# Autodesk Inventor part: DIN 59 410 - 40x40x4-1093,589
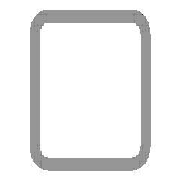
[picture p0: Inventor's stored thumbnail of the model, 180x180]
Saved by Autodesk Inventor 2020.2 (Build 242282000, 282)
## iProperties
Manager: www.cadconsulting.pl
Company: Fabian Stasiak CAD Consulting
IsCustomPart: 1
_CCFamilyMember: 20
_CCFamilyDisplayName: DIN 59410 (Kwadrat) - Rurki stalowe o przekroju kwadratowym formowane na gorąco
_FrameMemberDoc: Frame Member File
_Version: 15.0.0
_GetPNFromCC: 1
Created: 2015-01
Part Number: DIN 59 410 - 40x40x4-1093,589
Material: Stal, miękka
Description: Rurki stalowe o przekroju kwadratowym formowane na gorąco
Document SubType Name: Modellieren
Standard: DIN
Designer: F.Stasiak
Standards Organization: DIN
Language: pl-PL
Size Designation: 40x40x4
Categories: <MemberInstance><Categories><Category DisplayName="Kształtowniki konstrukcyjne" InternalName="089c4875-fa83-4c05-b084-43b9cc11f5ed" Mnemonic="GRDR"><CategoryPar
Stock Number: 40x40x4
Density: 7.85 g/cm^3
Appearance: Częściowo polerowana
Mass: 4393.44 g
Surface Area: 2813.5 cm^2
Volume: 559.674 cm^3
Catalog Web Link: www.expertbooks.pl
G_W: 40,000 mm
G_H: 40,000 mm
+F403492C-6B18-40DC-B024-0F370B1C1C0C+CUTDETAIL1: Wytnij
+DCBC0641-DB32-4E4F-ADE9-E62C8F4C886A+CUTDETAIL2: Wytnij
G_L: 1093,589 mm
Author: F.Stasiak
Subject: Zbiór ćwiczeń. Autodesk Inventor 2020. Kurs Professional
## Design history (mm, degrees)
node "Płaszczyzna początkowa"
node "Płaszczyzna końcowa"
sketch "Szkic1"
  geometry: L1 (-12, 20)-(12, 20); L2 (20, 12)-(20, -12); L3 (12, -20)-(-12, -20); L4 (-20, -12)-(-20, 12); L5 (-30.32, 0)-(30.32, 0) reference; L6 (0, -30.32)-(0, 30.32) reference; L7 (-12, 16)-(12, 16); L8 (16, 12)-(16, -12); L9 (12, -16)-(-12, -16); L10 (-16, -12)-(-16, 12); A1 r 8 centre (-12, 12) between (-12, 20) and (-20, 12); A2 r 8 centre (12, 12) between (20, 12) and (12, 20); A3 r 8 centre (12, -12) between (12, -20) and (20, -12); A4 r 8 centre (-12, -12) between (-20, -12) and (-12, -20); A5 r 4 centre (-12, 12) between (-12, 16) and (-16, 12); A6 r 4 centre (12, 12) between (16, 12) and (12, 16); A7 r 4 centre (12, -12) between (12, -16) and (16, -12); A8 r 4 centre (-12, -12) between (-16, -12) and (-12, -16); 3 further points
  constraints: 16 end point, 16 point on circle, 8 centre point, 8 tangent, 6 point on line, 4 parallel, 3 equal radius, 3 perpendicular, 1 horizontal, 7 other
  dimensions: "b" = 40 distance of point (-20, 20) point (20, 20); "msp_r" = 8 radius of A1 (= 2 x ParT); "d8" = 20 distance between parallel lines of L4 L6 (= d9); "d9" = 20 distance between parallel lines of L3 L5 (= 0.5 x b); "d10" = 4 distance between parallel lines of L3 L9 (= ParT)
extrude "Bryła" new body sketch "Szkic1" taper "d4" = 0 deg; stored distance "NLG" = 10
node "Driven Length"
  sketch "Sketch2"
    geometry: L1 (0, 0)-(10, 0) reference
    constraints: 2 end point, 1 horizontal
  workplane "Work Plane3"
  sketch "Sketch3"
    geometry: L1 (-2, 22.426)-(12, 22.426) reference; L2 (-2, 1116.016)-(12, 1116.016) reference
    dimensions: "d14" = 1093.5891 distance between parallel lines of L1 L2 (derived)
node "Płaszczyzna konstrukcyjna4"
feature "Podział1"
node "Płaszczyzna konstrukcyjna5"
feature "Podział2"
body "Solid1"
other parameters: "ParT" = 4, "G_OFFSET_START" = -22.42641 [user parameter; used in 1 equation term], "G_OFFSET_END" = -15.35534 [user parameter; used in 1 equation term], "d11" = 22.42641 (= -G_OFFSET_START), "d12" = 1116.01551 (= G_OFFSET_END + B_L), "G_L" = 1093.5891 (= d14) [user parameter], "B_L" = 1131.37085 [user parameter; used in 1 equation term], "d13" = 90 deg
